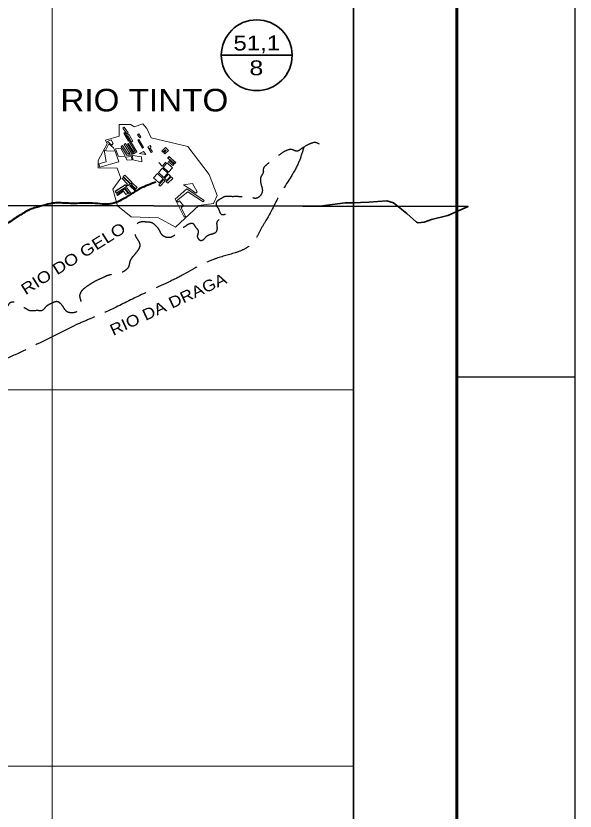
# Model space of a CAD drawing. Extents: x -4 to 42046, y -3 to 29697.
# Drawn here: x 39683 to 42046, y 13011 to 16374 of the extents above; entities that cross this region are included whole.
import ezdxf
from ezdxf.enums import TextEntityAlignment as Align

# ---------------------------------------------------------------- set-up
doc = ezdxf.new("R2010")
doc.units = 0
doc.header["$LTSCALE"] = 32
doc.linetypes.add('DOT_DASHED', pattern=[7.7, 5, -1.2, 0.3, -1.2])
doc.linetypes.add('LONG_DASHED', pattern=[7.5, 6, -1.5])
for name, color, linetype, lineweight in [('1', 7, 'DOT_DASHED', 13), ('3', 7, 'Continuous', 35), ('5', 7, 'LONG_DASHED', 25), ('6', 7, 'Continuous', 40), ('63', 7, 'Continuous', 25), ('9', 7, 'Continuous', 40)]:
    doc.layers.add(name, color=color, linetype=linetype, lineweight=lineweight)

msp = doc.modelspace()

# ---------------------------------------------------------------- linework, layer by layer
at = {"layer": '1', "linetype": 'Continuous'}
msp.add_line((40448.92, 15629.22), (40443.74, 15624.87), dxfattribs=at)
for points in [[(40518.62, 15580.09), (40456.07, 15571.45), (40357.4, 15480.67), (40285.41, 15520.2), (40170.39, 15524.09), (40112.75, 15571.27), (40093.09, 15641.4), (40126.78, 15688.01), (40111.43, 15730.25), (40030.25, 15730.85), (40030.49, 15762.97), (40068, 15833.29), (40061.19, 15847.64), (40119.49, 15864.73), (40119.34, 15914.62), (40169.28, 15914.77), (40182.79, 15904.66), (40219.96, 15917.46), (40236.93, 15898.06), (40236.93, 15898.06), (40254.81, 15857.52), (40408.82, 15821.62), (40499.65, 15703.5), (40532.89, 15614.8)], [(40134.89, 15899.11), (40151.94, 15875.54), (40157.13, 15879.28), (40140.08, 15902.85)], [(40139.01, 15877.71), (40159.04, 15844.55), (40163.27, 15847.1), (40143.24, 15880.26)], [(40154.91, 15870.75), (40171.97, 15840.9), (40177.14, 15843.85), (40160.08, 15873.7)], [(40196.98, 15871.24), (40206.25, 15858.35), (40211.34, 15862), (40202.07, 15874.89)], [(40069.73, 15842.44), (40085.94, 15850.24), (40093.75, 15834.04), (40087.86, 15826.99)], [(40167.54, 15843.84), (40162.38, 15839.39), (40186.86, 15800.71), (40181.5, 15797.33), (40157.73, 15834.89), (40154.05, 15832.57), (40180.57, 15790.66), (40194.16, 15799.24)], [(40198.16, 15847.99), (40217.82, 15814.46), (40222.64, 15817.28), (40202.98, 15850.81)], [(40037.2, 15734.19), (40033.47, 15748.21), (40064.6, 15756.49), (40055.81, 15805.49), (40065.42, 15802.93), (40101.96, 15801.2), (40118.33, 15756.95)], [(40103.41, 15811.91), (40117.16, 15779.46), (40144.84, 15781.02), (40126.65, 15814.93)], [(40174.34, 15789.23), (40146.53, 15834.18), (40140.27, 15830.32), (40165.36, 15789.78), (40158.47, 15789.92), (40152.92, 15795.07), (40133.63, 15825.28), (40128.45, 15821.98), (40151.89, 15785.27), (40172.51, 15784.43)], [(40254.3, 15796.68), (40239.9, 15819.75), (40250.34, 15826.25), (40254.6, 15819.41), (40249.18, 15816.04), (40259.54, 15799.43)], [(40311.64, 15790.28), (40307.5, 15794.4), (40317.72, 15804.66), (40314.87, 15807.49), (40304.35, 15796.92), (40299.38, 15801.86), (40314.93, 15817.48), (40327.56, 15804.93)], [(40146.7, 15776.6), (40153.01, 15763.33), (40172.2, 15765.23), (40170.8, 15779.35)], [(40214.67, 15757.24), (40176.63, 15765.25), (40176.21, 15782.96), (40213.5, 15777.9)], [(40231.93, 15787.93), (40205.71, 15791.54), (40222.3, 15799.71)], [(40353.61, 15747.97), (40325.36, 15772.74), (40330.39, 15778.46), (40358.64, 15753.7)], [(40352.54, 15747.64), (40325.55, 15773.69), (40330.27, 15778.57), (40357.26, 15752.52)], [(40328.48, 15712.87), (40305.33, 15733.55), (40322.28, 15752.49), (40345.43, 15731.82)], [(40328.35, 15757.09), (40345.81, 15740.51), (40350.67, 15745.63), (40333.21, 15762.21)], [(40304.63, 15685.28), (40281.49, 15707.2), (40264.8, 15689.62), (40287.94, 15667.7)], [(40285.24, 15711.57), (40307.41, 15690.51), (40324.46, 15708.41), (40302.29, 15729.48)], [(40320.17, 15678.41), (40336.94, 15695.49), (40328.05, 15704.2), (40311.27, 15687.13)], [(40154.81, 15655.55), (40151.11, 15659.23), (40154.79, 15662.93), (40132.02, 15685.57), (40137.36, 15690.93), (40165.31, 15663.15)], [(40174.05, 15669.14), (40142.75, 15700.25), (40136.69, 15694.17), (40167.99, 15663.06)], [(40308.06, 15681.86), (40287.22, 15658.91), (40292.77, 15653.88), (40313.61, 15676.84)], [(40346.17, 15686.71), (40325.29, 15666.1), (40318.65, 15672.81), (40339.52, 15693.42)], [(40102.21, 15632.52), (40144.6, 15659.52), (40149.65, 15651.62), (40106.59, 15624.2)], [(40102.84, 15630.67), (40145.94, 15659.22), (40150.58, 15652.22), (40107.48, 15623.67)], [(40112.85, 15614.83), (40138.27, 15632.25), (40147.44, 15618.89), (40155.33, 15624.3), (40142.94, 15642.33), (40109.03, 15619.08)], [(40145.99, 15642.24), (40162.29, 15622.72), (40167.48, 15627.05), (40151.18, 15646.57)], [(40186.62, 15633.87), (40164.04, 15654.84), (40167.4, 15658.45), (40189.98, 15637.48)], [(40171.77, 15660.03), (40189.55, 15642), (40195.33, 15647.69), (40177.56, 15665.72)]]:
    msp.add_lwpolyline(points, close=True, dxfattribs=at)
for points in [[(40061.07, 15804.09), (40076.03, 15832.12), (40095.64, 15816.31), (40101.96, 15801.2)], [(40286.51, 15753.96), (40301.29, 15738.56), (40315.97, 15755)], [(40478.3, 15593.49), (40404.74, 15643.09), (40355.71, 15599.02), (40393.95, 15523.1), (40400.24, 15526.26), (40380.72, 15562.39)], [(40448.92, 15629.22), (40429.75, 15664.7), (40391.63, 15659.39), (40391.63, 15659.39), (40417.68, 15642.13), (40443.74, 15624.87), (40443.74, 15624.87)], [(40380.72, 15562.39), (40390.53, 15570.29), (40373.69, 15591.16), (40367.34, 15586.05), (40362.21, 15592.4), (40409.2, 15630.21), (40473.73, 15586.92), (40478.3, 15593.49)]]:
    msp.add_lwpolyline(points, dxfattribs=at)
at = {"layer": '3'}
msp.add_lwpolyline([(40895.04, 15569.74), (40967.11, 15569.74), (41074.85, 15582.96), (41104.48, 15583.21), (41174.49, 15586.27), (41250.71, 15592.26), (41277.99, 15583.43), (41335.37, 15537.92), (41375.33, 15501.41), (41382.19, 15498.85), (41408.8, 15501.67), (41439.72, 15512.64), (41507.56, 15530.22), (41593.55, 15568.08), (38273.44, 15575.31)], dxfattribs=at)
msp.add_lwpolyline([(40895.04, 15569.74), (40967.11, 15569.74), (41074.85, 15582.96), (41104.48, 15583.21), (41174.49, 15586.27), (41250.71, 15592.26), (41277.99, 15583.43), (41335.37, 15537.92), (41375.33, 15501.41), (41382.19, 15498.85), (41408.8, 15501.67), (41439.72, 15512.64), (41507.56, 15530.22), (41593.55, 15568.08), (38273.44, 15575.31)], dxfattribs=at)
at = {"layer": '5'}
for points in [[(40965.01, 15831.67), (40947.62, 15838.27), (40924.72, 15832.29), (40891.88, 15813.71), (40868.26, 15801.81), (40852.72, 15807.68), (40821.31, 15802.04), (40779.63, 15773.09), (40741.28, 15743.77), (40728.4, 15725.99), (40728.43, 15714.17), (40718.88, 15694.55), (40718.98, 15661.28), (40724.24, 15633.2), (40711.74, 15609.51), (40702.15, 15603.2), (40674.68, 15607.86), (40657.96, 15613.02), (40643.46, 15609.69), (40621.56, 15609.62), (40592.54, 15609.54), (40565.72, 15609.46), (40548.22, 15600.1), (40536.2, 15592.67), (40529.93, 15584.99), (40529.97, 15571.3), (40537.39, 15560.92), (40542.63, 15548.61), (40549.51, 15536.31), (40557.73, 15533.6), (40572.79, 15533.64), (40572.82, 15523.79), (40563.52, 15521.02), (40550.11, 15517.97), (40539.18, 15510.27), (40532.36, 15501.77), (40532.42, 15484.52), (40532.45, 15471.38), (40528.11, 15459.32), (40514.72, 15451.62)], [(40899.44, 15817.95), (40879.23, 15757.84), (40808.06, 15634.18), (40739.69, 15509.13), (40713.18, 15462.76), (40690.86, 15422.01), (40531.16, 15348.59), (40371.48, 15269.56), (40221.6, 15198.98), (40098.33, 15138.29), (40000.27, 15094.51), (39939.89, 15068.67)], [(40514.72, 15451.62), (40492.86, 15444.31), (40478.25, 15430.53), (40469.72, 15423.79), (40461.79, 15423.77), (40454.75, 15431.07), (40451.06, 15440.22), (40454.34, 15465.26), (40446.07, 15476.22), (40439.63, 15486.27), (40432.89, 15494.19), (40416.02, 15494.14), (40393.97, 15480.82), (40376.38, 15470.19), (40364.66, 15458.64), (40352.48, 15446.15), (40340.28, 15438.13), (40317.02, 15438.06), (40305.02, 15443.9), (40296.29, 15454.21), (40288.26, 15469.93), (40274.34, 15486.34), (40259.1, 15498.02), (40233.37, 15502.05), (40209.61, 15501.98), (40196.41, 15495.69), (40187.34, 15482.09), (40184.37, 15460.82), (40188.71, 15442.26), (40201.28, 15421.75), (40206.87, 15403.19), (40202.98, 15389.79), (40191.06, 15372.96), (40181.45, 15361.14), (40171.02, 15348.25), (40164.24, 15333.89), (40160.53, 15317.3), (40153.6, 15304.89), (40142.9, 15295.94), (40128.31, 15287.54), (40105.36, 15281.92), (40076.15, 15277.51), (40050.85, 15266.83), (40018.21, 15252.01), (39998.55, 15240.05), (39978.24, 15226.56), (39958.82, 15207.89), (39952.37, 15190.99), (39958.52, 15163.73), (39952.54, 15136.44), (39939.59, 15122.98), (39921.42, 15117.73), (39898.03, 15123.72), (39882.81, 15144.02)], [(39883.95, 15142.5), (39869.71, 15158.89), (39856.21, 15165.47), (39838.33, 15160.27), (39813.12, 15146.96), (39792.59, 15127.53), (39775.67, 15127.48), (39740.62, 15127.37), (39725.4, 15135.66), (39708.21, 15145.17), (39692.57, 15157.77), (39655.02, 15157.65), (39646.49, 15145.03), (39632.16, 15132.38), (39627.94, 15109.44), (39613.15, 15083.94), (39591.78, 15065.22), (39573.25, 15060.7), (39551.47, 15053.52), (39529.02, 15038.3), (39519.2, 15020.37), (39513.28, 15004.06), (39513.35, 14981.33), (39518.43, 14971.48), (39522.82, 14960.01), (39530.66, 14950.63), (39542.38, 14944.92), (39553.86, 14942.43), (39568.79, 14939.03), (39574.79, 14929.64), (39566.78, 14919.75), (39548.94, 14900.87), (39526.73, 14882.22)], [(39939.72, 15068.81), (39760.3, 14979.43), (39575.54, 14897.75), (39524.46, 14880.41)]]:
    msp.add_spline(points, degree=3, dxfattribs=at)
at = {"layer": '6'}
msp.add_spline([(40273.96, 15670.56), (40208.64, 15643.85), (40145.69, 15604.72), (40113.58, 15588.24), (40097.16, 15582.42), (40075.13, 15578), (40047.99, 15577.92), (40007.24, 15582.01), (39969.93, 15581.89), (39895.72, 15581.67), (39837.99, 15581.5), (39799.17, 15571.76), (39749.81, 15557.78), (39703.44, 15533.09), (39653.44, 15500.84), (39606.44, 15470.15), (39555.14, 15435.73), (39507.09, 15404.55), (39448.73, 15366.82), (39371.29, 15315.2), (39280.63, 15254.37), (39206.92, 15204.91), (39181.36, 15187.93), (39164.98, 15177.13), (39156.29, 15167.72), (39146.84, 15153.73), (39134.81, 15134.78), (39127.62, 15122.36), (39105.06, 15085.78), (39066.37, 15023.76), (39039.28, 14980.22), (39030.15, 14966.68), (39026.28, 14960.3), (39019.54, 14955.37), (38998.81, 14946.28), (38974.69, 14934.84), (38946.98, 14924.24), (38926.48, 14914.89), (38909.31, 14907.25), (38887.25, 14893.63), (38872.8, 14884.41), (38858.94, 14875.56)], degree=3, dxfattribs=at)
at = {"layer": '63'}
for p, q in [((42045.8, -2.97), (42045.8, 29697.03)), ((42045.8, -2.97), (42045.8, 29697.03)), ((41545.8, 14847.03), (42045.8, 14847.03))]:
    msp.add_line(p, q, dxfattribs=at)
at = {"layer": '63', "lineweight": 13}
for p, q in [((39835.86, 10019.66), (39835.86, 18929.66)), ((41110.1, 14792.87), (23907.83, 14792.87)), ((41110.1, 13201.8), (23907.83, 13201.8))]:
    msp.add_line(p, q, dxfattribs=at)
at = {"layer": '63', "lineweight": 35}
msp.add_line((41110.1, 10019.66), (41110.1, 18929.66), dxfattribs=at)
at = {"layer": '63'}
msp.add_lwpolyline([(-4.21, -2.97), (42045.8, -2.97), (42045.8, 29697.03)], dxfattribs=at)
at = {"layer": '63', "lineweight": 60}
msp.add_lwpolyline([(1245.8, 29197.03), (41545.8, 29197.03), (41545.8, 497.03), (32795.79, 497.03)], dxfattribs=at)
at = {"layer": '9', "lineweight": 35}
msp.add_line((40551.01, 16207.34), (40850.28, 16207.34), dxfattribs=at)
msp.add_circle((40700.64, 16207.34), 149.63, dxfattribs=at)

# ---------------------------------------------------------------- texts
at = {"layer": '5'}
for s, height, rotation, width, p in [('RIO DO GELO', 47.75, 32.313, 1.2, (39723.89, 15192.14)), ('RIO DA DRAGA', 47.74, 24.819, 1.15, (40094.03, 15020.41))]:
    msp.add_text(s, height=height, rotation=rotation, dxfattribs=dict(at, width=width)).set_placement(p)
at = {"layer": '9'}
for s, width, p in [('51,1', 1.2, (40700.89, 16227.85)), ('8', 1.25, (40699.04, 16122.77))]:
    msp.add_text(s, height=63, rotation=0.17, dxfattribs=dict(at, width=width)).set_placement(p, align=Align.CENTER)
at = {"layer": '9', "width": 1.1}
msp.add_text('RIO TINTO', height=95.46, dxfattribs=at).set_placement((39870.82, 15969.93))

doc.saveas('drawing.dxf')
